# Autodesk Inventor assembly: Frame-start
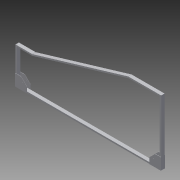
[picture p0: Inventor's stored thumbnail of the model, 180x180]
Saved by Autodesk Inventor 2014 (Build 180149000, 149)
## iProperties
Created: 2009-05
Part Number: Frame-start
Document SubType Name: Assembly
Designer: millerpa
Author: millerpa
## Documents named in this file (9)
- C:\Users\iTools\Desktop\tutorial files\iCopy\Frame-start.iam
- C:\Users\iTools\Desktop\tutorial files\iCopy\Skeleton-frame-start.ipt
- C:\Users\iTools\Desktop\tutorial files\iCopy\Frame1-start.ipt
- C:\Users\iTools\Desktop\tutorial files\iCopy\Frame2-start.ipt
- C:\Users\iTools\Desktop\tutorial files\iCopy\Frame3-start.ipt
- C:\Users\iTools\Desktop\tutorial files\iCopy\Frame4-start.ipt
- C:\Users\iTools\Desktop\tutorial files\iCopy\Frame5-start.ipt
- C:\Users\iTools\Desktop\tutorial files\iCopy\Frame6-start.ipt
- C:\Users\iTools\Desktop\tutorial files\iCopy\Plate1-start.ipt
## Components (11 placed, 8 different names)
1. Skeleton-frame-start:1 — Flush:1, Flush:2, Flush:3, Flush:4, Flush:5, Flush:6, Flush:7, Flush:8, Flush:9, Flush:10, Flush:11, Flush:12, Flush:13, Flush:14, Flush:15, Flush:16, Flush:17, Flush:18, Flush:19, Flush:20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
2. Frame1-start:1 — Flush:4, Flush:5, Flush:6, Mate:1, Flush:22, Mate:2, Flush:24
3. Frame2-start:1 — Flush:7, Flush:8, Flush:9
4. Frame3-start:1 — Flush:10, Flush:11, Flush:12
5. Frame4-start:1 — Flush:13, Flush:14, Flush:15
6. Frame5-start:1 — Flush:16, Flush:17, Flush:18, Flush:27, Flush:29
7. Frame6-start:1 — Flush:19, Flush:20, Flush:21, Flush:23, Flush:25, Mate:3, Flush:26, Mate:4, Flush:28
8. Plate1-start:1 — Mate:1, Flush:22, Flush:23
9. Plate1-start:2 — Mate:2, Flush:24, Flush:25
10. Plate1-start:3 — Mate:3, Flush:26, Flush:27
11. Plate1-start:4 — Mate:4, Flush:28, Flush:29
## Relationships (33: Flush 29, Mate 4)
- Flush:1: Skeleton-frame-start:1
- Flush:2: Skeleton-frame-start:1
- Flush:3: Skeleton-frame-start:1
- Flush:4: Skeleton-frame-start:1 ↔ Frame1-start:1
- Flush:5: Skeleton-frame-start:1 ↔ Frame1-start:1
- Flush:6: Skeleton-frame-start:1 ↔ Frame1-start:1
- Flush:7: Skeleton-frame-start:1 ↔ Frame2-start:1
- Flush:8: Skeleton-frame-start:1 ↔ Frame2-start:1
- Flush:9: Skeleton-frame-start:1 ↔ Frame2-start:1
- Flush:10: Skeleton-frame-start:1 ↔ Frame3-start:1
- Flush:11: Skeleton-frame-start:1 ↔ Frame3-start:1
- Flush:12: Skeleton-frame-start:1 ↔ Frame3-start:1
- Flush:13: Skeleton-frame-start:1 ↔ Frame4-start:1
- Flush:14: Skeleton-frame-start:1 ↔ Frame4-start:1
- Flush:15: Skeleton-frame-start:1 ↔ Frame4-start:1
- Flush:16: Skeleton-frame-start:1 ↔ Frame5-start:1
- Flush:17: Skeleton-frame-start:1 ↔ Frame5-start:1
- Flush:18: Skeleton-frame-start:1 ↔ Frame5-start:1
- Flush:19: Skeleton-frame-start:1 ↔ Frame6-start:1
- Flush:20: Skeleton-frame-start:1 ↔ Frame6-start:1
- Flush:21: Skeleton-frame-start:1 ↔ Frame6-start:1
- Mate:1: Frame1-start:1 ↔ Plate1-start:1
- Flush:22: Frame1-start:1 ↔ Plate1-start:1
- Flush:23: Frame6-start:1 ↔ Plate1-start:1
- Mate:2: Frame1-start:1 ↔ Plate1-start:2
- Flush:24: Frame1-start:1 ↔ Plate1-start:2
- Flush:25: Frame6-start:1 ↔ Plate1-start:2
- Mate:3: Frame6-start:1 ↔ Plate1-start:3
- Flush:26: Frame6-start:1 ↔ Plate1-start:3
- Flush:27: Frame5-start:1 ↔ Plate1-start:3
- Mate:4: Frame6-start:1 ↔ Plate1-start:4
- Flush:28: Frame6-start:1 ↔ Plate1-start:4
- Flush:29: Frame5-start:1 ↔ Plate1-start:4
